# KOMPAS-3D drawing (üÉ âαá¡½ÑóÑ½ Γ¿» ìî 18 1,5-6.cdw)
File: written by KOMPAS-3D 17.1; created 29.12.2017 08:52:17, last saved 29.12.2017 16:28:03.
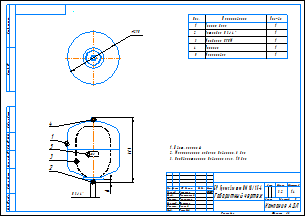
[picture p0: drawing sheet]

Sheet 1: A3, landscape, title-block layout from C:\Лощинин\GRAPHIC.LYT style 1

Title block, sheet 1: name: БР Гранлевел тип НМ 18/1,5-6 / Габаритный чертеж; mass: 3,2; sheets: 1; sheet format: A3; stored path: K:\АП\20_PKO\02_Насосное направление\Разработка\04_Проекты разные\Баки\КД действующая\Баки Flexcon R\Компас\Чертежи\БР Гранлевел тип НМ 18 1,5-6.cdw; drawn by: Лощинин; checked by: Хантимеров; drawn by, date: 29.12.2017

Views: Вид 1, Снизу, Проекционный вид 2
Referenced files in \\Fsk1\files\АП\20_PKO\02_Насосное направление\Разработка\04_Проекты разные\Баки\КД действующая\Баки Flexcon R\Компас\: 18 литров.a3d
Referenced files in C:\Лощинин\: GRAPHIC.LYT
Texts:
  IvAn
  ADL
  АДЛ
  Цвет: красный
  Максимальное рабочее давление: 6 бар
  Предварительное давление газа: 1,5 бар
  ACAD_ISO03W100_RGB_223_127_255_SC_0.063_THICK_0.05
  ACAD_ISO03W100_RGB_223_127_255_SC_1_THICK_0.05
  Лит-Масса-Масштаб
  Материал-Предприятие
  Масштаб
  Изм.
  Лист
  № докум.
  Подп.
  Дата
  Лит.
  Разраб.
  Пров.
  Т.контр.
  Курлыкина
  Листов
  Нач.отд.
  Щетинин
  Н.контр.
  Долгов
  Утв.
  Рашидов
  Компания АДЛ
  Изменение
  Номер документа
  Подпись
  Обозначение документа
  Наименование изделия
  Масса изделия по ГОСТ 2.109-73
  Порядковый номер листа
  Общее количество листов в документе
  Характер работы, выполненной лицом, подписавшим документ
  Наименование или индекс предприятия, выпускающего документ
  Инв. № подл.
  Подп. и дата
  Взам. инв. №
  Инв. № дубл.
  Инвентарный номер подлинника по ГОСТ 2.501-68
  Подпись принявшего подлинник в отдел технической документации
  Инвентарный номер подлинника, взамен которого выпущен данный подлинник
  Инвентарный номер дубликата по ГОСТ 2.502-68
  Подпись принявшего дубликат в отдел технической документации
  Справ. №
  Перв. примен.
  Обозначение документа, взамен или на основании которого выпущен данный документ
  Обозначение документа, в котором впервые записан данный документ
  Подпись лица, копировавшего чертеж
  Обозначение формата листа
Dimensions and other numbers on the sheet: 290; 357; 16; 4; 5; 1; 3; 2; 1:4; 3,2; 29.12.2017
